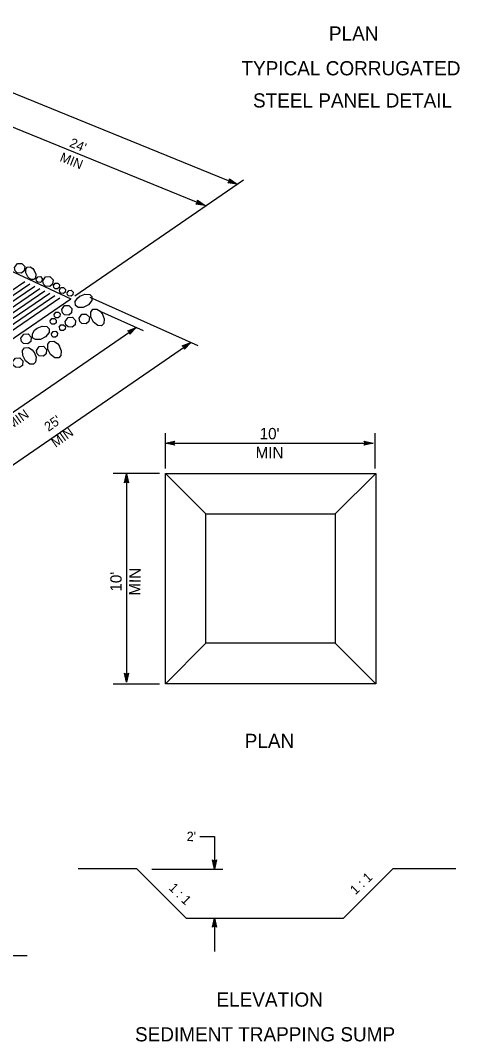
# Model space of a CAD drawing. Extents: x 6709491 to 6710959, y 1869789 to 1870763.
# Drawn here: x 6710044 to 6710323, y 1869789 to 1870438 of the extents above; entities that cross this region are included whole.
import ezdxf

# ---------------------------------------------------------------- set-up
doc = ezdxf.new("R2010")
doc.units = 0
for name, color, linetype in [('56 Stg 3 Anno', 7, 'Continuous'), ('57 Undefined', 7, 'Continuous'), ('60 Nongeo Data', 7, 'Continuous')]:
    doc.layers.add(name, color=color, linetype=linetype)

msp = doc.modelspace()

# ---------------------------------------------------------------- linework, layer by layer
at = {"layer": '56 Stg 3 Anno'}
for p, q in [((6709859.63, 1870464.61), (6710181.3, 1870333.54)), ((6710000.15, 1870385.54), (6710160.97, 1870320.01)), ((6710078.31, 1870262.74), (6710185.26, 1870336.25)), ((6710175.49, 1870334.53), (6710176.68, 1870335.42)), ((6710181.3, 1870333.54), (6710175.49, 1870334.53)), ((6710175.49, 1870334.53), (6710175.49, 1870334.53)), ((6710180.06, 1870334.04), (6710175.83, 1870334.76)), ((6710178.85, 1870334.54), (6710176.11, 1870335)), ((6710176.68, 1870335.42), (6710176.45, 1870336.9)), ((6710176.45, 1870336.9), (6710176.45, 1870336.9)), ((6710176.45, 1870336.9), (6710181.3, 1870333.54)), ((6710177.62, 1870335.04), (6710176.45, 1870335.24)), ((6710176.52, 1870336.51), (6710180.08, 1870334.04)), ((6710176.59, 1870336.1), (6710178.85, 1870334.54)), ((6710176.63, 1870335.73), (6710177.62, 1870335.04)), ((6710181.3, 1870333.54), (6710181.3, 1870333.54)), ((6710155.15, 1870321), (6710156.34, 1870321.89)), ((6710160.97, 1870320.01), (6710155.15, 1870321)), ((6710155.15, 1870321), (6710155.15, 1870321)), ((6710159.73, 1870320.51), (6710155.49, 1870321.24)), ((6710158.51, 1870321.01), (6710155.77, 1870321.48)), ((6710157.28, 1870321.51), (6710156.11, 1870321.71)), ((6710156.34, 1870321.89), (6710156.12, 1870323.38)), ((6710156.12, 1870323.38), (6710156.12, 1870323.38)), ((6710156.12, 1870323.38), (6710160.97, 1870320.01)), ((6710156.18, 1870322.98), (6710159.74, 1870320.51)), ((6710156.26, 1870322.58), (6710158.51, 1870321.01)), ((6710156.29, 1870322.2), (6710157.28, 1870321.51)), ((6710160.97, 1870320.01), (6710160.97, 1870320.01)), ((6710087.81, 1870261.86), (6710156.29, 1870231.14)), ((6710095.26, 1870252.59), (6710121.67, 1870240.75)), ((6709960.88, 1870135.33), (6710117.29, 1870242.71)), ((6710111.81, 1870240.51), (6710117.29, 1870242.71)), ((6710117.29, 1870242.71), (6710113.26, 1870238.4)), ((6710117.29, 1870242.71), (6710117.29, 1870242.71)), ((6710113.17, 1870239.89), (6710111.81, 1870240.51)), ((6710111.81, 1870240.51), (6710111.81, 1870240.51)), ((6710112.18, 1870240.35), (6710116.2, 1870241.96)), ((6710112.56, 1870240.19), (6710115.1, 1870241.21)), ((6710112.89, 1870240.01), (6710114.01, 1870240.46)), ((6710113.26, 1870238.4), (6710113.17, 1870239.89)), ((6710114.01, 1870240.46), (6710113.2, 1870239.59)), ((6710115.1, 1870241.21), (6710113.21, 1870239.18)), ((6710116.19, 1870241.95), (6710113.25, 1870238.81)), ((6710113.26, 1870238.4), (6710113.26, 1870238.4)), ((6709985.07, 1870118.55), (6710151.91, 1870233.1)), ((6710146.44, 1870230.9), (6710151.91, 1870233.1)), ((6710147.8, 1870230.28), (6710146.44, 1870230.9)), ((6710146.44, 1870230.9), (6710146.44, 1870230.9)), ((6710146.8, 1870230.74), (6710150.82, 1870232.35)), ((6710147.18, 1870230.58), (6710149.72, 1870231.6)), ((6710147.51, 1870230.4), (6710148.63, 1870230.85)), ((6710147.89, 1870228.79), (6710147.8, 1870230.28)), ((6710148.63, 1870230.85), (6710147.82, 1870229.98)), ((6710149.72, 1870231.6), (6710147.83, 1870229.57)), ((6710150.81, 1870232.34), (6710147.88, 1870229.2)), ((6710151.91, 1870233.1), (6710147.89, 1870228.79)), ((6710151.91, 1870233.1), (6710151.91, 1870233.1)), ((6710147.89, 1870228.79), (6710147.89, 1870228.79)), ((6710135.66, 1870175.49), (6710135.66, 1870153.14)), ((6710268.81, 1870175.49), (6710268.81, 1870153.14)), ((6710135.83, 1870169.28), (6710141.59, 1870170.56)), ((6710135.83, 1870169.28), (6710141.59, 1870170.56)), ((6710135.83, 1870169.28), (6710267.69, 1870169.28)), ((6710141.59, 1870168), (6710135.83, 1870169.28)), ((6710135.83, 1870169.28), (6710135.83, 1870169.28)), ((6710141.59, 1870168), (6710135.83, 1870169.28)), ((6710135.83, 1870169.28), (6710135.83, 1870169.28)), ((6710141.38, 1870168.34), (6710137.16, 1870169.28)), ((6710141.38, 1870168.34), (6710137.16, 1870169.28)), ((6710137.17, 1870169.28), (6710141.37, 1870170.21)), ((6710137.17, 1870169.28), (6710141.37, 1870170.21)), ((6710138.48, 1870169.28), (6710141.2, 1870169.88)), ((6710138.48, 1870169.28), (6710141.2, 1870169.88)), ((6710141.16, 1870168.68), (6710138.48, 1870169.28)), ((6710141.16, 1870168.68), (6710138.48, 1870169.28)), ((6710139.81, 1870169.28), (6710140.97, 1870169.54)), ((6710139.81, 1870169.28), (6710140.97, 1870169.54)), ((6710140.99, 1870169.02), (6710139.81, 1870169.28)), ((6710140.99, 1870169.02), (6710139.81, 1870169.28)), ((6710141.59, 1870170.56), (6710140.82, 1870169.28)), ((6710141.59, 1870170.56), (6710140.82, 1870169.28)), ((6710140.82, 1870169.28), (6710141.59, 1870168)), ((6710140.82, 1870169.28), (6710141.59, 1870168)), ((6710141.59, 1870170.56), (6710141.59, 1870170.56)), ((6710141.59, 1870170.56), (6710141.59, 1870170.56)), ((6710141.59, 1870168), (6710141.59, 1870168)), ((6710141.59, 1870168), (6710141.59, 1870168)), ((6710262.7, 1870169.28), (6710261.93, 1870170.57)), ((6710261.93, 1870170.57), (6710261.93, 1870170.57)), ((6710261.93, 1870170.57), (6710267.69, 1870169.28)), ((6710267.69, 1870169.28), (6710261.93, 1870168)), ((6710261.93, 1870168), (6710262.7, 1870169.28)), ((6710261.93, 1870168), (6710261.93, 1870168)), ((6710262.14, 1870170.23), (6710266.37, 1870169.28)), ((6710266.36, 1870169.28), (6710262.16, 1870168.35)), ((6710265.04, 1870169.28), (6710262.33, 1870168.68)), ((6710262.36, 1870169.88), (6710265.04, 1870169.28)), ((6710262.53, 1870169.55), (6710263.71, 1870169.28)), ((6710263.71, 1870169.28), (6710262.55, 1870169.03)), ((6710267.69, 1870169.28), (6710267.69, 1870169.28)), ((6710102.68, 1870150.28), (6710132.09, 1870150.28)), ((6710109.78, 1870144.02), (6710111.07, 1870149.78)), ((6710109.78, 1870144.02), (6710111.07, 1870149.78)), ((6710110.13, 1870144.23), (6710111.07, 1870148.45)), ((6710110.13, 1870144.23), (6710111.07, 1870148.45)), ((6710110.47, 1870144.45), (6710111.07, 1870147.13)), ((6710110.47, 1870144.45), (6710111.07, 1870147.13)), ((6710110.8, 1870144.62), (6710111.07, 1870145.8)), ((6710110.8, 1870144.62), (6710111.07, 1870145.8)), ((6710111.07, 1870149.78), (6710111.07, 1870017.51)), ((6710111.07, 1870149.78), (6710111.07, 1870149.78)), ((6710111.07, 1870149.78), (6710112.35, 1870144.02)), ((6710111.07, 1870149.78), (6710111.07, 1870149.78)), ((6710111.07, 1870149.78), (6710112.35, 1870144.02)), ((6710111.07, 1870148.44), (6710112, 1870144.24)), ((6710111.07, 1870148.44), (6710112, 1870144.24)), ((6710111.07, 1870147.13), (6710111.67, 1870144.41)), ((6710111.07, 1870147.13), (6710111.67, 1870144.41)), ((6710111.07, 1870145.8), (6710111.33, 1870144.64)), ((6710111.07, 1870145.8), (6710111.33, 1870144.64)), ((6710111.07, 1870144.79), (6710109.78, 1870144.02)), ((6710111.07, 1870144.79), (6710109.78, 1870144.02)), ((6710109.78, 1870144.02), (6710109.78, 1870144.02)), ((6710109.78, 1870144.02), (6710109.78, 1870144.02)), ((6710112.35, 1870144.02), (6710111.07, 1870144.79)), ((6710112.35, 1870144.02), (6710111.07, 1870144.79)), ((6710112.35, 1870144.02), (6710112.35, 1870144.02)), ((6710112.35, 1870144.02), (6710112.35, 1870144.02)), ((6710111.07, 1870017.51), (6710109.79, 1870023.27)), ((6710109.79, 1870023.27), (6710109.79, 1870023.27)), ((6710109.79, 1870023.27), (6710111.07, 1870022.51)), ((6710111.07, 1870018.85), (6710110.14, 1870023.05)), ((6710111.07, 1870020.17), (6710110.47, 1870022.88)), ((6710111.07, 1870021.49), (6710110.82, 1870022.65)), ((6710111.07, 1870022.51), (6710112.36, 1870023.27)), ((6710112.36, 1870023.27), (6710111.07, 1870017.51)), ((6710112.02, 1870023.07), (6710111.07, 1870018.84)), ((6710111.67, 1870022.84), (6710111.07, 1870020.17)), ((6710111.34, 1870022.67), (6710111.07, 1870021.49)), ((6710112.36, 1870023.27), (6710112.36, 1870023.27)), ((6710102.68, 1870016.4), (6710132.09, 1870016.4)), ((6710111.07, 1870017.51), (6710111.07, 1870017.51)), ((6710157.55, 1869919.67), (6710166.97, 1869919.67)), ((6710166.97, 1869919.67), (6710166.97, 1869898.98)), ((6710166.97, 1869898.98), (6710165.69, 1869904.74)), ((6710165.69, 1869904.74), (6710165.69, 1869904.74)), ((6710165.69, 1869904.74), (6710166.97, 1869903.97)), ((6710166.97, 1869900.31), (6710166.04, 1869904.51)), ((6710166.97, 1869901.63), (6710166.37, 1869904.34)), ((6710166.97, 1869902.95), (6710166.71, 1869904.11)), ((6710166.97, 1869903.97), (6710168.26, 1869904.74)), ((6710168.26, 1869904.74), (6710166.97, 1869898.98)), ((6710167.91, 1869904.53), (6710166.97, 1869900.3)), ((6710167.57, 1869904.3), (6710166.97, 1869901.63)), ((6710167.24, 1869904.13), (6710166.97, 1869902.95)), ((6710168.26, 1869904.74), (6710168.26, 1869904.74)), ((6710127.05, 1869898.98), (6710172.16, 1869898.98)), ((6710166.97, 1869898.98), (6710166.97, 1869898.98)), ((6710165.68, 1869862.07), (6710166.97, 1869867.83)), ((6710166.97, 1869867.83), (6710166.97, 1869846.68)), ((6710166.97, 1869867.83), (6710166.97, 1869867.83)), ((6710166.97, 1869867.83), (6710168.25, 1869862.07)), ((6710166.97, 1869862.83), (6710165.68, 1869862.07)), ((6710165.68, 1869862.07), (6710165.68, 1869862.07)), ((6710166.02, 1869862.27), (6710166.97, 1869866.5)), ((6710166.37, 1869862.5), (6710166.97, 1869865.17)), ((6710166.7, 1869862.67), (6710166.97, 1869863.85)), ((6710166.97, 1869866.49), (6710167.9, 1869862.29)), ((6710166.97, 1869865.17), (6710167.57, 1869862.46)), ((6710166.97, 1869863.85), (6710167.22, 1869862.69)), ((6710168.25, 1869862.07), (6710166.97, 1869862.83)), ((6710168.25, 1869862.07), (6710168.25, 1869862.07))]:
    msp.add_line(p, q, dxfattribs=at)
msp.add_lwpolyline([(6710040.02, 1870280.7), (6710041.76, 1870283.17), (6710044.53, 1870283.33), (6710046.46, 1870281.33), (6710046.18, 1870278.52), (6710044.47, 1870277.1), (6710041.73, 1870277.3), (6710040.44, 1870278.55), (6710040.02, 1870280.7)], dxfattribs=at)
at = {"layer": '60 Nongeo Data'}
for p, q in [((6710025.41, 1870284.39), (6710075.72, 1870260.77)), ((6709974, 1870222.49), (6710046.53, 1870271.93)), ((6709977.18, 1870221), (6710049.65, 1870270.4)), ((6709980.36, 1870219.51), (6710052.87, 1870268.93)), ((6709983.54, 1870218.01), (6710056.01, 1870267.4)), ((6709986.72, 1870216.52), (6710059.22, 1870265.93)), ((6709989.9, 1870215.03), (6710062.35, 1870264.41)), ((6709993.08, 1870213.53), (6710065.47, 1870262.87)), ((6709996.27, 1870212.04), (6710068.76, 1870261.45)), ((6709998.31, 1870208.01), (6710075.72, 1870260.77)), ((6710161.46, 1870124.39), (6710135.78, 1870150.07)), ((6710243.64, 1870124.39), (6710269.32, 1870150.07)), ((6710135.78, 1870016.54), (6710161.46, 1870042.22)), ((6710243.64, 1870042.22), (6710269.32, 1870016.54)), ((6710080.44, 1869899.37), (6710117.47, 1869899.37)), ((6710117.47, 1869899.37), (6710149, 1869867.83)), ((6710248.81, 1869867.83), (6710280.35, 1869899.37)), ((6710280.35, 1869899.37), (6710320.12, 1869899.37)), ((6710149, 1869867.83), (6710248.81, 1869867.83)), ((6709754.44, 1869844.14), (6710047.92, 1869844.14))]:
    msp.add_line(p, q, dxfattribs=at)
for points in [[(6710052.46, 1870278.84), (6710053.43, 1870276.4), (6710053.23, 1870274.16), (6710052.22, 1870273.09), (6710050.4, 1870273.12), (6710048.33, 1870274.74), (6710047.08, 1870277.24), (6710047.04, 1870279.6), (6710047.98, 1870280.92), (6710049.86, 1870281.05), (6710051.54, 1870279.97), (6710052.52, 1870278.74)], [(6710053.69, 1870273.4), (6710054.74, 1870274.88), (6710056.4, 1870274.97), (6710057.56, 1870273.77), (6710057.39, 1870272.09), (6710056.36, 1870271.24), (6710054.72, 1870271.35), (6710053.94, 1870272.1), (6710053.69, 1870273.4)], [(6710057.95, 1870272.28), (6710059.69, 1870274.76), (6710062.47, 1870274.91), (6710064.4, 1870272.91), (6710064.12, 1870270.11), (6710062.4, 1870268.68), (6710059.66, 1870268.88), (6710058.37, 1870270.13), (6710057.95, 1870272.28)], [(6710064.67, 1870269.24), (6710065.72, 1870270.72), (6710067.38, 1870270.82), (6710068.54, 1870269.61), (6710068.37, 1870267.93), (6710067.34, 1870267.08), (6710065.7, 1870267.19), (6710064.93, 1870267.95), (6710064.67, 1870269.24)], [(6710068.43, 1870266.44), (6710069.47, 1870267.92), (6710071.14, 1870268.02), (6710072.3, 1870266.82), (6710072.13, 1870265.13), (6710071.1, 1870264.28), (6710069.45, 1870264.4), (6710068.68, 1870265.15), (6710068.43, 1870266.44)], [(6710073.31, 1870264.69), (6710074.35, 1870266.17), (6710076.02, 1870266.27), (6710077.18, 1870265.07), (6710077.01, 1870263.38), (6710075.98, 1870262.53), (6710074.33, 1870262.65), (6710073.56, 1870263.4), (6710073.31, 1870264.69)], [(6710081.44, 1870262.56), (6710084.7, 1870263.85), (6710087.69, 1870263.59), (6710089.11, 1870262.24), (6710089.06, 1870259.82), (6710086.9, 1870257.06), (6710083.57, 1870255.4), (6710080.43, 1870255.34), (6710078.66, 1870256.6), (6710078.5, 1870259.1), (6710079.93, 1870261.33), (6710081.58, 1870262.65)], [(6710069.92, 1870254.03), (6710071.66, 1870256.51), (6710074.43, 1870256.66), (6710076.36, 1870254.66), (6710076.09, 1870251.86), (6710074.37, 1870250.43), (6710071.63, 1870250.63), (6710070.34, 1870251.88), (6710069.92, 1870254.03)], [(6710065.09, 1870250.86), (6710066.14, 1870252.34), (6710067.8, 1870252.44), (6710068.96, 1870251.24), (6710068.79, 1870249.55), (6710067.76, 1870248.7), (6710066.12, 1870248.82), (6710065.34, 1870249.57), (6710065.09, 1870250.86)], [(6710072.21, 1870246.46), (6710073.95, 1870248.93), (6710076.72, 1870249.09), (6710078.65, 1870247.09), (6710078.37, 1870244.28), (6710076.66, 1870242.86), (6710073.92, 1870243.05), (6710072.63, 1870244.31), (6710072.21, 1870246.46)], [(6710081.03, 1870248.55), (6710082.77, 1870251.02), (6710085.54, 1870251.18), (6710087.48, 1870249.18), (6710087.2, 1870246.37), (6710085.48, 1870244.95), (6710082.74, 1870245.15), (6710081.45, 1870246.4), (6710081.03, 1870248.55)], [(6710095.58, 1870251.43), (6710096.87, 1870248.18), (6710096.61, 1870245.19), (6710095.26, 1870243.77), (6710092.84, 1870243.81), (6710090.08, 1870245.97), (6710088.41, 1870249.3), (6710088.36, 1870252.44), (6710089.61, 1870254.21), (6710092.12, 1870254.37), (6710094.35, 1870252.94), (6710095.66, 1870251.3)], [(6710054.24, 1870242.15), (6710057.5, 1870243.44), (6710060.49, 1870243.18), (6710061.91, 1870241.83), (6710061.86, 1870239.4), (6710059.7, 1870236.65), (6710056.37, 1870234.98), (6710053.23, 1870234.93), (6710051.46, 1870236.18), (6710051.3, 1870238.68), (6710052.73, 1870240.92), (6710054.37, 1870242.23)], [(6710062.6, 1870246.87), (6710063.64, 1870248.35), (6710065.31, 1870248.45), (6710066.47, 1870247.25), (6710066.3, 1870245.57), (6710065.27, 1870244.71), (6710063.63, 1870244.83), (6710062.85, 1870245.58), (6710062.6, 1870246.87)], [(6710068.41, 1870242.84), (6710069.46, 1870244.32), (6710071.13, 1870244.41), (6710072.28, 1870243.21), (6710072.12, 1870241.53), (6710071.09, 1870240.68), (6710069.44, 1870240.79), (6710068.67, 1870241.54), (6710068.42, 1870242.84)], [(6710044.05, 1870235.93), (6710045.79, 1870238.41), (6710048.57, 1870238.57), (6710050.5, 1870236.57), (6710050.22, 1870233.76), (6710048.5, 1870232.33), (6710045.76, 1870232.53), (6710044.47, 1870233.78), (6710044.05, 1870235.93)], [(6710063.38, 1870238.63), (6710064.42, 1870240.11), (6710066.09, 1870240.21), (6710067.25, 1870239.01), (6710067.08, 1870237.32), (6710066.05, 1870236.47), (6710064.4, 1870236.59), (6710063.63, 1870237.34), (6710063.38, 1870238.63)], [(6710052.35, 1870226.96), (6710053.64, 1870223.71), (6710053.38, 1870220.72), (6710052.03, 1870219.3), (6710049.61, 1870219.34), (6710046.85, 1870221.5), (6710045.19, 1870224.83), (6710045.13, 1870227.97), (6710046.39, 1870229.74), (6710048.89, 1870229.91), (6710051.13, 1870228.48), (6710052.44, 1870226.83)], [(6710053.83, 1870228.13), (6710055.57, 1870230.61), (6710058.34, 1870230.77), (6710060.27, 1870228.76), (6710060, 1870225.96), (6710058.28, 1870224.53), (6710055.54, 1870224.73), (6710054.25, 1870225.98), (6710053.83, 1870228.13)], [(6710068.38, 1870231.02), (6710069.67, 1870227.76), (6710069.41, 1870224.77), (6710068.06, 1870223.35), (6710065.64, 1870223.4), (6710062.88, 1870225.55), (6710061.21, 1870228.89), (6710061.16, 1870232.03), (6710062.41, 1870233.79), (6710064.92, 1870233.96), (6710067.15, 1870232.53), (6710068.46, 1870230.88)], [(6710038.77, 1870220.78), (6710040.51, 1870223.26), (6710043.28, 1870223.42), (6710045.22, 1870221.41), (6710044.94, 1870218.61), (6710043.22, 1870217.18), (6710040.48, 1870217.38), (6710039.19, 1870218.63), (6710038.77, 1870220.78)]]:
    msp.add_lwpolyline(points, dxfattribs=at)
for points in [[(6710269.32, 1870016.54), (6710135.78, 1870016.54), (6710135.78, 1870150.07), (6710269.32, 1870150.07)], [(6710243.64, 1870042.22), (6710161.46, 1870042.22), (6710161.46, 1870124.39), (6710243.64, 1870124.39)]]:
    msp.add_lwpolyline(points, close=True, dxfattribs=at)

# ---------------------------------------------------------------- texts
at = {"layer": '57 Undefined'}
for s, p in [('PLAN', (6710239.61, 1870424.69)), ('TYPICAL CORRUGATED', (6710184.06, 1870402.66)), ('STEEL PANEL DETAIL', (6710191.39, 1870382.24)), ('PLAN', (6710186.12, 1869975.78)), ('ELEVATION', (6710168.19, 1869811.63)), ('SEDIMENT TRAPPING SUMP', (6710116.48, 1869789.59))]:
    msp.add_text(s, height=9, dxfattribs=at).set_placement(p)
for s, height, rotation, p in [("24'", 6, 337.82938, (6710074.37, 1870357.58)), ('MIN', 6, 337.82938, (6710068.24, 1870348.42)), ('MIN', 6, 35.46566, (6710037.7, 1870177.72)), ("25'", 6, 35.46566, (6710061.56, 1870176.35)), ('MIN', 6, 35.46566, (6710066.02, 1870166.26)), ("10'", 7.2, 359.6363, (6710195.62, 1870171.72)), ('MIN', 7.2, 359.6363, (6710193.06, 1870159.73)), ("10'", 7.2, 89.6363, (6710107.93, 1870075.02)), ('MIN', 7.2, 89.6363, (6710119.91, 1870072.45)), ("2'", 6, 359.6363, (6710149.25, 1869916.67)), ('1 : 1', 6, 43.25519, (6710256.41, 1869882.34)), ('1 : 1', 6, 315.66558, (6710137.41, 1869886.5))]:
    msp.add_text(s, height=height, rotation=rotation, dxfattribs=at).set_placement(p)

doc.saveas('drawing.dxf')
